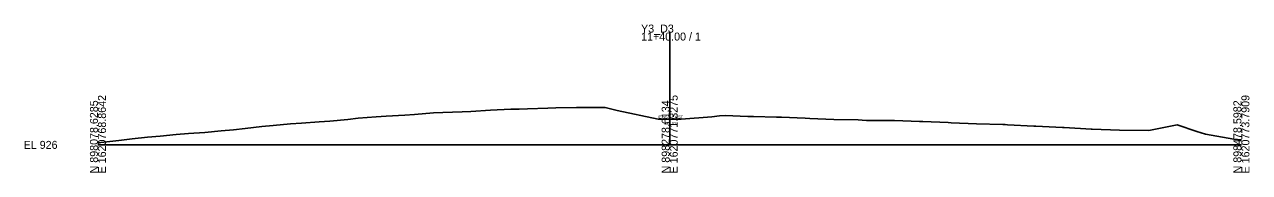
# Model space of a CAD drawing. Extents: x 162 to 3321, y 3 to 7010.
# Drawn here: x 2892.7 to 3321.2, y 1932.9 to 1984.8 of the extents above; entities that cross this region are included whole.
import ezdxf

# ---------------------------------------------------------------- set-up
doc = ezdxf.new("R2010")
doc.units = 0
for name, color, linetype in [('Exist Cross Section Cell', 7, 'Continuous'), ('Exist XS Center Line Elevation Label', 7, 'Continuous'), ('Exist XS Ground Line', 7, 'Continuous'), ('Prop XS SE Text', 7, 'Continuous')]:
    doc.layers.add(name, color=color, linetype=linetype)

msp = doc.modelspace()

# ---------------------------------------------------------------- linework, layer by layer
at = {"layer": 'Exist Cross Section Cell'}
for p, q in [((3118.38, 1942.6), (3118.38, 1981.95)), ((2918.38, 1942.6), (3118.38, 1942.6)), ((3118.38, 1942.6), (3318.38, 1942.6))]:
    msp.add_line(p, q, dxfattribs=at)
at = {"layer": 'Exist XS Ground Line'}
msp.add_lwpolyline([(2918.38, 1943.31), (2920.44, 1943.55), (2925.74, 1944.16), (2930.32, 1944.67), (2935.74, 1945.34), (2940.2, 1945.71), (2945.74, 1946.24), (2950.08, 1946.61), (2955.74, 1946.95), (2961.54, 1947.54), (2965.74, 1947.87), (2969.84, 1948.35), (2975.74, 1949.04), (2979.72, 1949.42), (2985.74, 1949.99), (2989.6, 1950.17), (2995.74, 1950.64), (2999.48, 1950.94), (3005.75, 1951.55), (3009.36, 1951.94), (3015.75, 1952.38), (3019.24, 1952.69), (3025.75, 1953.05), (3029.12, 1953.19), (3035.75, 1953.77), (3039, 1953.93), (3045.75, 1954.13), (3048.88, 1954.32), (3055.75, 1954.8), (3062.8, 1955.13), (3065.75, 1955.17), (3068.64, 1955.28), (3075.75, 1955.52), (3078.52, 1955.6), (3085.75, 1955.71), (3088.4, 1955.72), (3095.76, 1955.68), (3100.06, 1954.7), (3114.39, 1951.61), (3118.38, 1951.61), (3119.42, 1951.61), (3122.4, 1951.61), (3133.12, 1952.48), (3135.76, 1952.76), (3137.79, 1952.87), (3145.76, 1952.5), (3147.67, 1952.49), (3155.76, 1952.35), (3157.55, 1952.3), (3165.76, 1951.97), (3167.43, 1951.88), (3175.77, 1951.47), (3184.31, 1951.38), (3185.77, 1951.23), (3187.19, 1951.13), (3195.77, 1951.12), (3197.07, 1951.09), (3205.77, 1950.77), (3206.95, 1950.74), (3215.77, 1950.4), (3216.83, 1950.36), (3225.77, 1950.03), (3234.94, 1949.74), (3235.77, 1949.72), (3236.59, 1949.68), (3245.77, 1949.14), (3246.47, 1949.11), (3255.78, 1948.69), (3256.35, 1948.65), (3265.78, 1948.1), (3266.23, 1948.1), (3275.78, 1947.71), (3285.99, 1947.68), (3295.87, 1949.58), (3302.8, 1947.31), (3305.78, 1946.33), (3315.78, 1944.56), (3318.38, 1944.4)], dxfattribs=at)

# ---------------------------------------------------------------- texts
at = {"layer": 'Exist Cross Section Cell'}
for s, p in [('Y3_D3', (3108.38, 1981.95)), ('11+40.00 / 1', (3108.38, 1979.15)), ('EL 926', (2892.38, 1941.2))]:
    msp.add_text(s, height=2.8, dxfattribs=at).set_placement(p)
for s, p in [('E 1620768.8642', (2921.18, 1932.6)), ('E 1620771.3275', (3121.18, 1932.6)), ('E 1620773.7909', (3321.18, 1932.6)), ('N 898078.6285', (2918.38, 1932.6)), ('N 898278.6134', (3118.38, 1932.6)), ('N 898478.5982', (3318.38, 1932.6))]:
    msp.add_text(s, height=2.8, rotation=90, dxfattribs=at).set_placement(p)
at = {"layer": 'Exist XS Center Line Elevation Label'}
msp.add_text('935.01', height=1, dxfattribs=at).set_placement((3116.42, 1949.56))
at = {"layer": 'Prop XS SE Text'}
for rotation, p in [(1.1458, (3114.48, 1951.85)), (358.8542, (3119.06, 1951.94))]:
    msp.add_text('EXIST', height=1, rotation=rotation, dxfattribs=at).set_placement(p)

doc.saveas('drawing.dxf')
